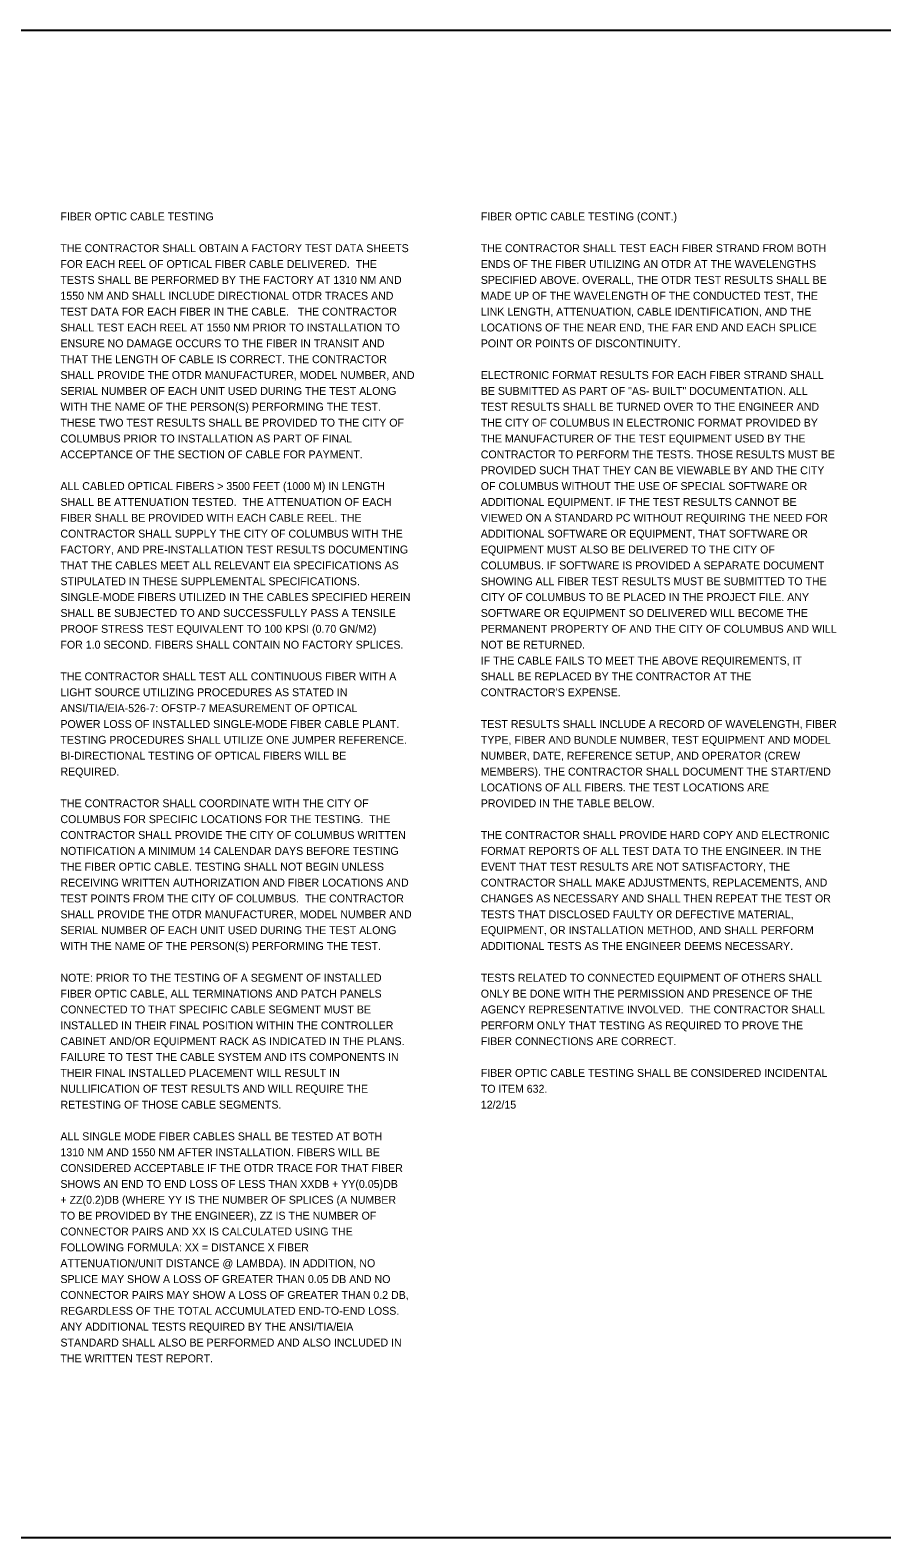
# Model space of a CAD drawing. Extents: x -41.3 to 53.7, y -40.1 to 14.5.
# Drawn here: x -2.11 to 12.93, y -40.09 to -13.47 of the extents above; entities that cross this region are included whole.
import ezdxf

# ---------------------------------------------------------------- set-up
doc = ezdxf.new("R2010")
doc.units = 0
doc.layers.add('SH_Data', color=7, linetype='Continuous')
doc.layers.add('SH_Text', color=7, linetype='Continuous')

msp = doc.modelspace()

# ---------------------------------------------------------------- linework, layer by layer
at = {"layer": 'SH_Text'}
msp.add_lwpolyline([(-41.349, -13.474), (32.055, -13.474), (32.055, -40.091), (-41.349, -40.091)], close=True, dxfattribs=at)

# ---------------------------------------------------------------- texts
at = {"layer": 'SH_Data'}
for s, p in [('FIBER OPTIC CABLE TESTING', (-1.574, -16.833)), ('FIBER OPTIC CABLE TESTING (CONT.)', (5.846, -16.833))]:
    msp.add_text(s, height=0.14, dxfattribs=at).set_placement(p)
at = {"layer": 'SH_Text'}
for s, p in [('THE CONTRACTOR SHALL OBTAIN A FACTORY TEST DATA SHEETS ', (-1.574, -17.393)), ('THE CONTRACTOR SHALL TEST EACH FIBER STRAND FROM BOTH ', (5.846, -17.393)), ('FOR EACH REEL OF OPTICAL FIBER CABLE DELIVERED.  THE ', (-1.574, -17.673)), ('ENDS OF THE FIBER UTILIZING AN OTDR AT THE WAVELENGTHS ', (5.846, -17.673)), ('TESTS SHALL BE PERFORMED BY THE FACTORY AT 1310 NM AND ', (-1.574, -17.953)), ('SPECIFIED ABOVE. OVERALL, THE OTDR TEST RESULTS SHALL BE ', (5.846, -17.953)), ('1550 NM AND SHALL INCLUDE DIRECTIONAL OTDR TRACES AND ', (-1.574, -18.233)), ('MADE UP OF THE WAVELENGTH OF THE CONDUCTED TEST, THE ', (5.846, -18.233)), ('TEST DATA FOR EACH FIBER IN THE CABLE.   THE CONTRACTOR ', (-1.574, -18.513)), ('LINK LENGTH, ATTENUATION, CABLE IDENTIFICATION, AND THE ', (5.846, -18.513)), ('SHALL TEST EACH REEL AT 1550 NM PRIOR TO INSTALLATION TO ', (-1.574, -18.793)), ('LOCATIONS OF THE NEAR END, THE FAR END AND EACH SPLICE ', (5.846, -18.793)), ('ENSURE NO DAMAGE OCCURS TO THE FIBER IN TRANSIT AND ', (-1.574, -19.073)), ('POINT OR POINTS OF DISCONTINUITY. ', (5.846, -19.073)), ('THAT THE LENGTH OF CABLE IS CORRECT. THE CONTRACTOR ', (-1.574, -19.353)), ('SHALL PROVIDE THE OTDR MANUFACTURER, MODEL NUMBER, AND ', (-1.574, -19.633)), ('ELECTRONIC FORMAT RESULTS FOR EACH FIBER STRAND SHALL ', (5.846, -19.633)), ('SERIAL NUMBER OF EACH UNIT USED DURING THE TEST ALONG ', (-1.574, -19.913)), ('BE SUBMITTED AS PART OF "AS- BUILT" DOCUMENTATION. ALL ', (5.846, -19.913)), ('WITH THE NAME OF THE PERSON(S) PERFORMING THE TEST.  ', (-1.574, -20.193)), ('TEST RESULTS SHALL BE TURNED OVER TO THE ENGINEER AND ', (5.846, -20.193)), ('THESE TWO TEST RESULTS SHALL BE PROVIDED TO THE CITY OF ', (-1.574, -20.473)), ('THE CITY OF COLUMBUS IN ELECTRONIC FORMAT PROVIDED BY ', (5.846, -20.473)), ('COLUMBUS PRIOR TO INSTALLATION AS PART OF FINAL ', (-1.574, -20.753)), ('THE MANUFACTURER OF THE TEST EQUIPMENT USED BY THE ', (5.846, -20.753)), ('ACCEPTANCE OF THE SECTION OF CABLE FOR PAYMENT. ', (-1.574, -21.033)), ('CONTRACTOR TO PERFORM THE TESTS. THOSE RESULTS MUST BE ', (5.846, -21.033)), ('PROVIDED SUCH THAT THEY CAN BE VIEWABLE BY AND THE CITY ', (5.846, -21.313)), ('ALL CABLED OPTICAL FIBERS > 3500 FEET (1000 M) IN LENGTH ', (-1.574, -21.593)), ('OF COLUMBUS WITHOUT THE USE OF SPECIAL SOFTWARE OR ', (5.846, -21.593)), ('SHALL BE ATTENUATION TESTED.  THE ATTENUATION OF EACH ', (-1.574, -21.873)), ('ADDITIONAL EQUIPMENT. IF THE TEST RESULTS CANNOT BE ', (5.846, -21.873)), ('FIBER SHALL BE PROVIDED WITH EACH CABLE REEL. THE ', (-1.574, -22.153)), ('VIEWED ON A STANDARD PC WITHOUT REQUIRING THE NEED FOR ', (5.846, -22.153)), ('CONTRACTOR SHALL SUPPLY THE CITY OF COLUMBUS WITH THE ', (-1.574, -22.433)), ('ADDITIONAL SOFTWARE OR EQUIPMENT, THAT SOFTWARE OR ', (5.846, -22.433)), ('FACTORY, AND PRE-INSTALLATION TEST RESULTS DOCUMENTING ', (-1.574, -22.713)), ('EQUIPMENT MUST ALSO BE DELIVERED TO THE CITY OF ', (5.846, -22.713)), ('THAT THE CABLES MEET ALL RELEVANT EIA SPECIFICATIONS AS ', (-1.574, -22.993)), ('COLUMBUS. IF SOFTWARE IS PROVIDED A SEPARATE DOCUMENT ', (5.846, -22.993)), ('STIPULATED IN THESE SUPPLEMENTAL SPECIFICATIONS.', (-1.574, -23.273)), ('SHOWING ALL FIBER TEST RESULTS MUST BE SUBMITTED TO THE ', (5.846, -23.273)), ('SINGLE-MODE FIBERS UTILIZED IN THE CABLES SPECIFIED HEREIN ', (-1.574, -23.553)), ('CITY OF COLUMBUS TO BE PLACED IN THE PROJECT FILE. ANY ', (5.846, -23.553)), ('SHALL BE SUBJECTED TO AND SUCCESSFULLY PASS A TENSILE ', (-1.574, -23.833)), ('SOFTWARE OR EQUIPMENT SO DELIVERED WILL BECOME THE ', (5.846, -23.833)), ('PROOF STRESS TEST EQUIVALENT TO 100 KPSI (0.70 GN/M2) ', (-1.574, -24.113)), ('PERMANENT PROPERTY OF AND THE CITY OF COLUMBUS AND WILL ', (5.846, -24.113)), ('FOR 1.0 SECOND. FIBERS SHALL CONTAIN NO FACTORY SPLICES.', (-1.574, -24.393)), ('NOT BE RETURNED.', (5.846, -24.393)), ('IF THE CABLE FAILS TO MEET THE ABOVE REQUIREMENTS, IT ', (5.846, -24.673)), ('THE CONTRACTOR SHALL TEST ALL CONTINUOUS FIBER WITH A ', (-1.574, -24.953)), ('SHALL BE REPLACED BY THE CONTRACTOR AT THE ', (5.846, -24.953)), ('LIGHT SOURCE UTILIZING PROCEDURES AS STATED IN ', (-1.574, -25.233)), ("CONTRACTOR'S EXPENSE. ", (5.846, -25.233)), ('ANSI/TIA/EIA-526-7: OFSTP-7 MEASUREMENT OF OPTICAL ', (-1.574, -25.513)), ('POWER LOSS OF INSTALLED SINGLE-MODE FIBER CABLE PLANT.  ', (-1.574, -25.793)), ('TEST RESULTS SHALL INCLUDE A RECORD OF WAVELENGTH, FIBER ', (5.846, -25.793)), ('TESTING PROCEDURES SHALL UTILIZE ONE JUMPER REFERENCE. ', (-1.574, -26.073)), ('TYPE, FIBER AND BUNDLE NUMBER, TEST EQUIPMENT AND MODEL ', (5.846, -26.073)), ('BI-DIRECTIONAL TESTING OF OPTICAL FIBERS WILL BE ', (-1.574, -26.353)), ('NUMBER, DATE, REFERENCE SETUP, AND OPERATOR (CREW ', (5.846, -26.353)), ('REQUIRED.  ', (-1.574, -26.633)), ('MEMBERS). THE CONTRACTOR SHALL DOCUMENT THE START/END ', (5.846, -26.633)), ('LOCATIONS OF ALL FIBERS. THE TEST LOCATIONS ARE ', (5.846, -26.913)), ('THE CONTRACTOR SHALL COORDINATE WITH THE CITY OF ', (-1.574, -27.193)), ('PROVIDED IN THE TABLE BELOW.', (5.846, -27.193)), ('COLUMBUS FOR SPECIFIC LOCATIONS FOR THE TESTING.  THE ', (-1.574, -27.473)), ('CONTRACTOR SHALL PROVIDE THE CITY OF COLUMBUS WRITTEN ', (-1.574, -27.753)), ('THE CONTRACTOR SHALL PROVIDE HARD COPY AND ELECTRONIC ', (5.846, -27.753)), ('NOTIFICATION A MINIMUM 14 CALENDAR DAYS BEFORE TESTING ', (-1.574, -28.033)), ('FORMAT REPORTS OF ALL TEST DATA TO THE ENGINEER. IN THE ', (5.846, -28.033)), ('THE FIBER OPTIC CABLE. TESTING SHALL NOT BEGIN UNLESS ', (-1.574, -28.313)), ('EVENT THAT TEST RESULTS ARE NOT SATISFACTORY, THE ', (5.846, -28.313)), ('RECEIVING WRITTEN AUTHORIZATION AND FIBER LOCATIONS AND ', (-1.574, -28.593)), ('CONTRACTOR SHALL MAKE ADJUSTMENTS, REPLACEMENTS, AND ', (5.846, -28.593)), ('TEST POINTS FROM THE CITY OF COLUMBUS.  THE CONTRACTOR ', (-1.574, -28.873)), ('CHANGES AS NECESSARY AND SHALL THEN REPEAT THE TEST OR ', (5.846, -28.873)), ('SHALL PROVIDE THE OTDR MANUFACTURER, MODEL NUMBER AND ', (-1.574, -29.153)), ('TESTS THAT DISCLOSED FAULTY OR DEFECTIVE MATERIAL, ', (5.846, -29.153)), ('SERIAL NUMBER OF EACH UNIT USED DURING THE TEST ALONG ', (-1.574, -29.433)), ('EQUIPMENT, OR INSTALLATION METHOD, AND SHALL PERFORM ', (5.846, -29.433)), ('WITH THE NAME OF THE PERSON(S) PERFORMING THE TEST.  ', (-1.574, -29.713)), ('ADDITIONAL TESTS AS THE ENGINEER DEEMS NECESSARY.', (5.846, -29.713)), ('NOTE: PRIOR TO THE TESTING OF A SEGMENT OF INSTALLED ', (-1.574, -30.273)), ('TESTS RELATED TO CONNECTED EQUIPMENT OF OTHERS SHALL ', (5.846, -30.273)), ('FIBER OPTIC CABLE, ALL TERMINATIONS AND PATCH PANELS ', (-1.574, -30.553)), ('ONLY BE DONE WITH THE PERMISSION AND PRESENCE OF THE ', (5.846, -30.553)), ('CONNECTED TO THAT SPECIFIC CABLE SEGMENT MUST BE ', (-1.574, -30.833)), ('AGENCY REPRESENTATIVE INVOLVED.  THE CONTRACTOR SHALL ', (5.846, -30.833)), ('INSTALLED IN THEIR FINAL POSITION WITHIN THE CONTROLLER ', (-1.574, -31.113)), ('PERFORM ONLY THAT TESTING AS REQUIRED TO PROVE THE ', (5.846, -31.113)), ('CABINET AND/OR EQUIPMENT RACK AS INDICATED IN THE PLANS. ', (-1.574, -31.393)), ('FIBER CONNECTIONS ARE CORRECT.', (5.846, -31.393)), ('FAILURE TO TEST THE CABLE SYSTEM AND ITS COMPONENTS IN ', (-1.574, -31.673)), ('THEIR FINAL INSTALLED PLACEMENT WILL RESULT IN ', (-1.574, -31.953)), ('FIBER OPTIC CABLE TESTING SHALL BE CONSIDERED INCIDENTAL ', (5.846, -31.953)), ('NULLIFICATION OF TEST RESULTS AND WILL REQUIRE THE ', (-1.574, -32.233)), ('TO ITEM 632.', (5.846, -32.233)), ('RETESTING OF THOSE CABLE SEGMENTS.', (-1.574, -32.513)), ('12/2/15', (5.846, -32.513)), ('ALL SINGLE MODE FIBER CABLES SHALL BE TESTED AT BOTH ', (-1.574, -33.073)), ('1310 NM AND 1550 NM AFTER INSTALLATION. FIBERS WILL BE ', (-1.574, -33.353)), ('CONSIDERED ACCEPTABLE IF THE OTDR TRACE FOR THAT FIBER ', (-1.574, -33.633)), ('SHOWS AN END TO END LOSS OF LESS THAN XXDB + YY(0.05)DB ', (-1.574, -33.913)), ('+ ZZ(0.2)DB (WHERE YY IS THE NUMBER OF SPLICES (A NUMBER ', (-1.574, -34.193)), ('TO BE PROVIDED BY THE ENGINEER), ZZ IS THE NUMBER OF ', (-1.574, -34.473)), ('CONNECTOR PAIRS AND XX IS CALCULATED USING THE ', (-1.574, -34.753)), ('FOLLOWING FORMULA: XX = DISTANCE X FIBER ', (-1.574, -35.033)), ('ATTENUATION/UNIT DISTANCE @ LAMBDA). IN ADDITION, NO ', (-1.574, -35.313)), ('SPLICE MAY SHOW A LOSS OF GREATER THAN 0.05 DB AND NO ', (-1.574, -35.593)), ('CONNECTOR PAIRS MAY SHOW A LOSS OF GREATER THAN 0.2 DB, ', (-1.574, -35.873)), ('REGARDLESS OF THE TOTAL ACCUMULATED END-TO-END LOSS. ', (-1.574, -36.153)), ('ANY ADDITIONAL TESTS REQUIRED BY THE ANSI/TIA/EIA ', (-1.574, -36.433)), ('STANDARD SHALL ALSO BE PERFORMED AND ALSO INCLUDED IN ', (-1.574, -36.713)), ('THE WRITTEN TEST REPORT.', (-1.574, -36.993))]:
    msp.add_text(s, height=0.14, rotation=360, dxfattribs=at).set_placement(p)

doc.saveas('drawing.dxf')
